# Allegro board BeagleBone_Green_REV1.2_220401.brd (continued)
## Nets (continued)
Pads without a net: J1 2 3 6; NOREF#4 1; NOREF#8 1; NOREF#13 1; NOREF#15 1; NOREF#22 1; NOREF#23 1; NOREF#26 1; NOREF#32 1; NOREF#33 1; NOREF#34 1; NOREF#35 1; NOREF#37 1; NOREF#38 1; NOREF#39 1; P2 6; P5 7; P10 S2; U2 14 15 16 17 35 36 37 38 44; U3 1; U5 F16 M5 M15 P18; U6 1; U9 3 5; U10 5; U12 J1 J9 L1 L9; U13 A1 A2 A7 A8 A9 A10 A11 A12 A13 A14 B1 B7 B8 B9 B10 B11 B12 B13 B14 C1 C3 C5 C7 C8 C9 C10 C11 C12 C13 C14 D1 D2 D3 D4 D12 D13 D14 E1 E2 E3 E5 E8 E9 E10 E12 E13 E14 F1 F2 F3 F10 F12 F13 F14 G1 G2 G3 G10 G12 G13 G14 H1 H2 H3 H5 H12 H13 H14 J1 J2 J3 J12 J13 J14 K1 K2 K3 K6 K7 K10 K12 K13 K14 L1 L2 L3 L12 L13 L14 M1 M2 M3 M7 M8 M9 M10 M11 M12 M13 M14 N1 N3 N6 N7 N8 N9 N10 N11 N12 N13 N14 P1 P2 P7 P8 P9 P10 P11 P12 P13 P14; U16 1

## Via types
v1: diameter 0.457, hole 0.203, TOP to BOTTOM, 899 vias
v2: diameter 0.559, hole 0.305, TOP to BOTTOM, 20 vias

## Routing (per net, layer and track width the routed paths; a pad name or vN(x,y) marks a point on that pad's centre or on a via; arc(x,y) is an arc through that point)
DGND: length 387.2
  TOP w0.076: U13.N2 27.05,44.91 26.85,44.91 26.84,44.91 26.7,44.91 26.69,44.92 26.33,44.92
  TOP w0.178: U13.N5 27.02,43.44 U13.P4
  TOP w0.191: U10.4 v1(14.1,41.41)
  TOP w0.203: U13.C4 32.06,43.43 32,43.43 v1(31.78,43.2) ; U13.H10 29.7,40.56 29.7,40.28 29.84,40.13 29.84,40.11 v1(29.85,40.11) ; v1(31.75,42.01) 31.71,42.05 31.41,42.05 U13.E7 ; U13.P4 25.58,43.66 v1(25.1,44.15) ; v1(28.25,41.66) 28.26,41.66 U13.K8 ; U2.41 v1(23.46,19.62) ; U2.30 24.46,15.04 24.26,15.24 v2(23.88,15.24) ; U13.P6 26.18,42.66 v1(26.04,42.52) ; v1(33.81,42.12) 33.3,42.63 U13.A6 ; v1(25.5,44.7) 26.11,44.7 26.33,44.92 ; U13.G5 30.24,43.16 29.79,43.6 v1(29.79,43.69) 29.5,43.69 29.3,43.48 U13.J5
  TOP w0.254: U5.M7 v1(48.12,30.81) U5.M6 ; v1(46.52,30.01) U5.K9 ; v1(44.92,31.61) U5.M10 ; U5.V18 38.99,36.08 v1(38.99,36.83) ; U12.B9 v1(67.1,30.37) U12.A9 ; v1(61.5,30.37) U12.B3 ; U5.K7 U5.J7 v1(48.12,28.41) ; U12.E2 v1(60.7,27.97) U12.D1 ; U5.J11 v1(44.12,28.41) ; U5.N14 v1(41.72,31.61) U5.M14 ; U5.L13 v1(43.32,30.81) U5.L12 ; v1(66.3,27.97) U12.E8 ; v1(48.12,32.41) U5.N7 ; U5.L10 v1(44.92,30.01) ; v1(44.92,30.01) U5.K10 ; v1(44.92,30.01) U5.K11 ; v1(59.9,30.37) U12.B1 ; v1(46.52,28.41) U5.J9 ; v1(66.3,28.77) U12.D8 ; U5.N10 v1(44.92,32.41) U5.N11 ; U5.H9 v1(46.52,27.61) U5.G8 ; R30.1 v1(51.71,17.75) ; U5.L11 v1(44.12,30.81) U5.M12 ; U5.G11 44.36,27.05 43.88,27.05 U5.G12 v1(43.32,26.81) ; U5.H7 v1(48.12,27.61) ; v1(43.32,27.61) U5.H12 ; U12.G1 59.31,26.96 59.31,27.3 59.69,27.69 60.18,27.69 U12.E1 v1(60.7,27.17) ; U5.H6 v1(48.92,28.41) U5.J6 ; v1(66.3,26.37) U12.G8 ; v1(67.1,19.96) U12.P9 ; U5.J10 v1(44.92,28.41) U5.H10 ; v1(59.9,18.36) U12.T1 ; U12.F9 v1(67.1,26.37) U12.G9 ; U5.M8 v1(46.52,31.61) U5.M9 ; U5.F8 v1(46.52,26.81) U5.G9 ; v1(47.32,28.41) U5.J8 ; v1(66.3,23.96) U12.J8 ; U5.A1 v1(52.52,21.72) ; v1(67.1,18.36) U12.T9 ; v1(59.9,21.56) U12.M1 ; v1(67.1,21.56) U12.M9 ; U5.A18 v1(38.52,22.01) ; v1(52.6,36.58) 52.52,36.49 U5.V1 ; v1(47.32,27.61) U5.H8 ; v1(60.7,23.96) U12.J2 ; v1(59.9,19.96) U12.P1
  TOP w0.381: 37.34,40.01 v1(37.34,39.88) 37.47,39.75 C159.2 38.61,39.75 38.73,39.62 ; 56.52,12.8 56.49,12.83 C96.1 C155.1 55.63,11.68 55.73,11.68 v1(56.01,11.4) ; v1(30.25,9.91) 30.66,9.91 30.88,9.69 U16.3 ; 20.57,41.05 20.95,41.43 R79.2 ; 20.57,41.05 22.58,41.05 v1(23.6,40.03) ; 20.57,41.05 19.02,41.05 18.8,41.27 R78.2 ; R84.2 v1(56.26,45.92) ; v1(20.95,7.24) 20.95,8.26 C1.1 21.59,8.13 v1(21.59,7.24) ; C24.2 44.2,15.06 v1(44.2,14.1) ; v1(22.1,21.34) 21.46,20.7 21.46,20.32 ; S1.3 v1(7.95,50.47) ; R81.2 52.96,42.8 v1(53.09,42.67) ; R118.2 30.53,24.89 v1(30.68,24.74) 31.19,24.74 31.62,24.31 C5.2 ; R118.2 29.97,24.26 ; R118.2 29.46,24.89 ; Y3.4 22.68,26.64 v1(22.28,26.24) 22.28,24.38 22.76,23.9 27,23.9 ; v1(26.99,7.11) 26.99,8.19 C12.1 26.61,8.32 26.29,8 26.29,7.18 v1(26.35,7.11) ; v1(34.29,6.48) C29.2 ; 29.59,19.56 29.46,19.43 27.69,19.43 ; S3.1 v1(7.95,44.37) ; R25.2 36.39,9.08 36.07,8.76 v1(36.07,8.57) ; 27,23.9 27.02,23.92 Y3.2 ; 27,23.9 27.81,23.9 28.19,24.28 v1(28.19,26.24) ; C61.1 v1(75.06,48.39) ; R95.2 75.95,46.23 v1(76.45,45.72) ; 21.97,43.05 R77.2 21.72,44.45 21.34,44.83 21.34,45.34 v1(21.21,45.47) 20.7,45.47 20.59,45.35 Q1.4 ; R80.2 v1(53.98,45.85) ; S2.4 v1(72.14,42.75) ; S2.2 v1(75.69,42.75) ; C18.2 v1(18.29,19.56) ; R93.2 R92.2 72.39,46.35 v1(71.75,45.72) ; Q1.1 19.29,43.63 v1(18.57,44.35) 18.44,44.48 18.08,44.48 17.92,44.64 Q2.4 ; U3.3 v1(40.99,43.43) ; v1(73.79,45.85) 74.17,46.23 R94.2 ; v1(46.35,12.59) R165.2 ; C6.2 v1(44.58,41.71) ; Q2.1 16.62,43.65 16.41,43.87 v1(15.93,43.87) ; S1.1 v1(7.95,51.36) ; S3.3 v1(8.89,39.73) ; C57.1 v1(55.12,48.46)
  TOP w0.508: C24.2 44.3,15.95 D7.1
  TOP w0.889: Y4.2 41.43,42.1 ; Y4.2 40.78,42.66 ; Y4.2 40.78,41.54
  LYR2_GND w0.889: P9.2 20.42,5.18 ; P9.2 18.95,5.18 ; P9.2 20.42,3.71 ; 16.54,7.39 TP8.1 ; TP8.1 18.01,7.39 ; TP8.1 16.54,8.86 ; TP8.1 18.01,8.86 ; P9.44 73.76,5.18 ; P9.44 73.76,3.71 ; P9.44 72.29,3.71 ; P9.44 72.29,5.18 ; 74.83,3.71 P9.46 ; P9.46 76.3,5.18 ; P9.46 74.83,5.18 ; 59.44,11.4 TP1.1 ; TP1.1 60.91,9.93 ; TP1.1 59.44,9.93 ; TP1.1 60.91,11.4 ; 18.72,51.13 P8.1 ; P8.1 18.72,49.2 ; P8.1 20.65,49.2 ; P8.1 20.65,51.13 ; 9.62,8.97 P3.4 ; P3.4 9.62,7.65 ; P3.4 10.95,7.65 ; P3.4 10.95,8.97 ; 73.76,2.64 P9.43 72.29,2.64 ; 16.41,26.13 P5.8 ; P5.8 17.88,24.67 ; P5.8 16.41,24.67 ; P5.8 17.88,26.13 ; 18.95,51.97 P8.2 20.42,51.97 ; 41.58,6.65 J1.1 ; J1.1 43.51,6.65 ; J1.1 41.58,8.59
  LYR2_GND w1.27: P9.45 P9.46 ; P8.2 P8.1 ; P9.43 P9.44 ; P9.1 P9.2
  LYR5_PWR w0.889: 74.83,3.71 P9.46 ; P9.46 76.3,3.71 ; P9.46 74.83,5.18 ; P9.46 76.3,5.18 ; 73.76,2.64 P9.43 72.29,2.64 ; 72.29,3.71 P9.44 ; P9.44 73.76,5.18 ; P9.44 73.76,3.71 ; P9.44 72.29,5.18
  BOTTOM w0.191: C88.2 45.71,23.5 44.92,24.3 v1(44.92,24.41) ; v1(29.21,32.7) 29.21,32.35 29.34,32.23 30.86,32.23 30.99,32.1 R115.2
  BOTTOM w0.203: C100.2 48.81,25.94 49.26,25.5 49.43,25.5 v1(49.72,25.21) ; v1(13.56,6.81) 12.06,8.31 R173.2
  BOTTOM w0.254: 70.74,15.93 R146.1 ; R146.1 70.74,17.6 ; R146.1 69.96,16.76 ; C70.1 42.63,26.12 v1(43.32,26.81) v1(43.32,27.61) ; v1(54.48,10.16) 53.21,10.16 52.83,10.54 52.83,11.43 52.08,12.18 U15.4 50.28,12.18 50.04,11.94 50.04,10.92 50.28,10.68 U15.1 ; C155.1 55.75,11.94 56.01,11.68 v1(56.01,11.4) ; v1(12.83,15.75) 13.22,15.36 U9.4 ; C127.2 v1(25.4,40.64) ; v1(31.75,42.01) 31.14,41.4 C129.2 ; v1(28.25,41.66) 29.01,42.42 C128.2 ; 14.1,17.02 v1(13.21,17.02)
  BOTTOM w0.305: C43.2 47.43,32.41 v1(48.12,32.41) C73.1 ; C46.2 44.63,29.72 v1(44.92,30.01) ; C48.2 47.83,28.7 v1(48.12,28.41) ; C60.1 v1(43.32,27.61) ; C94.2 v1(44.12,30.81) ; C63.2 44.01,26.81 v1(43.32,26.81) ; v1(46.52,30.01) 45.83,30.01 C47.2 ; C66.2 41.72,30.92 v1(41.72,31.61) 41.72,32.3 C41.2 ; v1(44.92,28.41) 45.58,28.41 C49.2 ; v1(48.12,30.81) C97.2 ; C72.1 46.23,26.52 v1(46.52,26.81) ; v1(46.52,31.61) 46.23,31.9 C42.2 ; v1(48.92,28.41) 48.92,29.1 C98.2 ; C99.2 v1(48.12,27.61) ; C50.2 v1(47.32,27.61)
  BOTTOM w0.381: 33.78,20.33 33.78,21.21 C62.1 33.02,21.21 33.02,20.33 ; 33.78,20.33 C64.2 ; 33.78,20.33 33.02,20.33 ; C81.2 47.88,37.54 v1(47.32,38.1) 46.99,37.77 C84.2 ; 33.02,20.33 v1(33.02,20.32) ; C71.1 38.73,37.08 v1(38.99,36.83) ; C115.2 69.49,29.57 v1(69.82,29.24) ; D6.1 v1(10.77,48.18) ; R117.2 R116.2 v1(31.75,27.94) ; R132.1 R130.1 v1(6.22,30.12) R135.2 v1(6.22,28.88) ; C126.1 23.5,40.13 v1(23.6,40.03) ; C137.2 11.77,34.07 11.77,33.91 12.02,33.66 v1(12.06,33.66) ; v2(22.61,13.97) 22.61,13.44 C146.2 ; R83.2 v1(60.71,43.31) ; v1(18.64,48.77) 18.16,48.29 U4.6 ; R90.2 v1(67.77,44.07) R91.2 ; v1(14.27,11.86) 14.27,12.4 14.78,12.9 C2.1 v1(15.34,11.81) ; C107.2 v1(57.15,31.17) ; C59.2 C90.2 C91.2 C89.2 C105.2 C92.2 ; C111.2 v1(57.15,23.16) ; v1(36.83,33.66) 37.15,33.97 R49.1 ; v1(40.64,39.62) 39.75,40.51 38.86,40.51 ; R88.2 R87.2 v1(64.14,43.31) ; v1(16.54,37.41) 16.13,37.82 R10.2 ; v1(36.83,26.81) C54.2 ; C54.2 C44.2 ; C54.2 C79.2 C69.1 ; v1(12.67,43.69) C36.2 13.46,44.2 v1(13.21,44.45) ; v1(30.23,37.08) 29.65,37.66 U1.3 ; v1(49.21,18.41) 50.87,18.41 51.12,18.66 R54.1 ; v1(49.21,18.41) C104.2 C92.2 ; v1(49.21,18.41) R164.2 ; v1(31.78,43.2) 32.39,43.81 C130.2 ; R12.1 v1(3.12,17.4) ; v1(5.84,45.82) 5.83,45.82 5.44,45.43 P4.5 ; P2.20 39.56,18.73 40.53,17.76 40.53,16.27 40.24,15.98 39.5,15.98 39.35,16.13 38.01,16.13 P2.16 v1(36.07,16.19) ; C56.1 45.72,35.53 45.82,35.63 v1(45.82,36.83) 44.45,36.83 43.96,37.32 C106.2 C58.2 ; U4.8 v1(20.7,48.16) ; v1(22.28,26.24) C142.2 ; v1(17.42,37.39) 17.02,37.8 C19.2 ; C109.2 v1(57.15,27.17) ; v1(3.73,16.7) 4.37,16.07 C35.2 ; C30.2 30,10.16 v1(30.25,9.91) ; v1(36.7,35.66) 36.75,35.61 37.21,35.61 37.58,35.24 C86.2 ; C117.2 69.35,25.57 v1(69.88,25.04) ; C143.2 v1(28.19,26.24) ; C92.2 v1(48.26,18.53) ; R82.2 v1(59.18,44.07) ; v1(5.31,6.55) 4.7,6.55 R53.2 ; R99.1 v1(69.85,21.96) ; v1(37.34,39.88) 37.11,39.88 U6.3 ; C38.2 C67.2 v1(33.02,35.56) ; C78.2 35.05,33.91 v1(35.56,33.91) ; v1(36.83,30.81) 36.87,30.77 37.55,30.77 C87.2 C45.2 ; v1(40.99,43.43) 40.69,43.73 C158.2 ; C114.2 v1(69.09,31.75) ; C108.2 v1(57.15,29.57) ; R29.1 49.17,38.86 48.92,38.61 v1(48.92,38.1) C68.1 ; v1(29.46,20.7) 29.46,21.46 29.91,21.91 U7.2 ; C141.2 v1(10.67,30.48) ; C61.1 v1(75.06,48.39) ; v1(5.59,9.78) 5.59,8.96 5.6,8.95 U8.1 ; C119.2 v1(69.85,24.36) ; P2.12 P2.10 36.32,12.38 36.07,12.13 v1(36.07,11.18) 36.13,11.11 P2.8 ; C77.2 33.34,37.08 v1(32.38,37.08) ; C110.2 v1(57.15,25.57) 57.06,25.65 R22.1 ; v1(66.3,23.96) U12.J8 C123.2 ; v1(62.99,21.21) C124.2 R100.2 ; C121.2 v1(69.85,19.16) ; v1(69.93,25.93) 70.1,26.11 C118.1 ; C135.2 27.81,33.66 27.84,33.63 v1(27.99,33.63) ; v1(41.35,38) 41.35,37.81 41.32,37.78 C80.2 ; 70.7,34.56 P10.6 v1(69.22,34.56) ; R144.2 v1(18.73,28.26) ; U4.7 v1(19.43,48.15) ; v1(50.16,38.1) 50.52,37.74 C74.1 ; v1(36.83,24.89) 36.84,24.89 36.96,24.77 C82.2 C83.2 C85.2 ; v1(17.6,49.12) 16.89,48.41 U4.5 ; v1(76.33,26.16) R147.1 v1(75.31,25.15) ; C17.2 C20.2 18.92,37.44 v1(18.87,37.39) 18.87,35.23 19.3,34.8 20.83,34.8 21.46,35.43 21.46,37.85 21.84,38.23 C27.2 24.84,38.28 C23.2 ; v1(31.24,40.13) 31.75,40.64 C145.2 C144.2 ; R86.2 v1(62.87,43.23) ; 25.91,30.48 26.16,30.23 C136.2 ; C75.1 v1(53.09,48.39) ; C113.2 v1(57.15,19.16) ; R85.2 v1(61.98,43.31) ; C154.2 v1(66.17,36.58) ; C140.2 v1(10.67,27.94) ; R145.2 v1(31.75,34.61) ; P2.4 v1(36.07,8.57) ; C112.2 v1(57.15,20.76) ; C152.2 v1(26.04,23.06) ; C138.2 v1(10.67,33.02) ; C139.2 v1(10.67,31.75) ; C120.2 v1(69.85,20.76) ; 65.91,37.97 v1(64.9,37.97) ; C116.2 v1(69.8,28.57) 71.68,28.57 72.19,29.09 P10.9 ; R89.2 v1(66.29,43.33) ; C125.2 v1(32.38,48.26) ; C28.2 v1(57.15,28.41) ; R96.1 v1(69.85,23.16) ; 43.43,14.86 v1(43.43,14.1) v1(44.2,14.1) 44.2,14.86 FB3.2 43.43,14.86
  vias: v1(3.81,32.13) v1(6.2,46.15) v1(6.43,45.72) v1(6.73,46.08) v1(6.99,28.7) v1(8.99,44.22) v1(12.61,19.12) v1(13.11,19.38) v1(15.62,16.26) v1(28.57,2.13) v1(29.97,18.03) v1(29.97,17.4) v1(31.06,2.08) v1(33.02,27.37) v1(33.02,26.54) v1(33.02,24.38) v1(39.98,41.33) v1(52.83,18.41) v1(55.37,16.76) v1(58.72,35.1) v1(60.2,35.05) v1(61.72,9.02) v1(61.85,11.05) v1(61.98,35.05) v1(63.17,15.82) v1(64.01,8.26) v1(65.41,10.67) v1(65.51,15.88) v1(67.64,8.05) v1(69.9,7.52) v1(71.5,6.22) v1(74.55,13.34) v1(74.8,6.22) v1(76.96,37.97) v1(79.63,38.86) v1(81.03,13.72) v1(81.15,22.35) v1(81.15,19.3) v1(81.15,15.49) v1(81.53,32.77) v1(81.79,37.08) v1(81.79,35.43) v1(81.92,26.04) v1(82.35,14.71) v1(83.06,37.21) v1(83.31,35.2) v1(83.29,33.3) v1(83.34,22.15) v1(83.36,25.91) v1(83.57,17.91) v2(3.99,11.71) v2(3.99,10.44) v2(5.26,11.71) v2(5.26,10.44) v2(21.51,13.56) v2(22.61,15.24) v2(24.13,31.11) v2(25.08,32.07) v2(25.08,31.11) v2(25.08,30.16) v2(26.04,31.11) v2(50.93,45.34) v2(51.69,46.23)
GND_EARTH: length 15.3
  BOTTOM w0.762: P4.9 3.16,47.35 3.34,47.53 P4.6 ; P10.S1 82.88,43.71 83.03,43.87
  vias: v1(0.79,33.68) v1(0.79,30.23) v1(0.81,22.07) v1(0.79,14.86) v1(0.81,8.18) v1(0.94,36.45) v1(0.94,18.64) v1(0.86,11.79) v1(0.99,25.68) v1(1.07,4.88) v1(1.24,50.62) v1(1.22,49.3) v1(1.19,45.62) v1(1.42,43.21) v1(1.37,39.34) v1(2.24,51.94) v1(2.24,51.28) v1(2.18,50.57) v1(2.18,49.91) v1(2.24,49.17) v1(2.29,23.19) v1(2.26,3.2) v1(3.35,40.44) v1(3.89,38.63) v1(4.52,39.4) v1(5.24,38.61) v1(5.71,40.39) v1(7.57,2.33) v1(8.31,20.68) v1(9.78,1.17) v1(11.3,2.67) v1(17.04,53.54) v1(17.04,1.07) v1(21.26,0.69) v1(23.65,53.92) v1(26.09,0.66) v1(28.63,53.98) v1(31.34,0.61) v1(33.58,53.95) v1(36.25,0.61) v1(38.71,53.95) v1(41.45,0.64) v1(43.74,53.95) v1(46.33,0.61) v1(48.97,53.92) v1(51.38,0.61) v1(54.13,53.98) v1(56.34,0.56) v1(59.05,53.92) v1(61.49,0.61) v1(64.26,53.92) v1(66.45,0.64) v1(69.29,53.92) v1(71.37,0.61) v1(74.4,53.95) v1(77.27,1.88) v1(77.52,52.58) v1(77.8,49.73) v1(83.34,45.75) v1(83.46,8.84) v1(84,43.92) v1(84.79,11.3) v1(84.94,41.78) v1(84.91,36.91) v1(84.89,32.18) v1(84.99,40.13) v1(85.09,26.7) v1(85.14,25.27) v1(85.12,14.66) v1(85.24,34.87) v1(85.24,29.34) v1(85.17,22.25) v1(85.24,16.54) v1(85.55,31.7) v1(85.5,19.08)
GND_OSC0: length 30.3
  TOP w0.121: 44.52,36.83 U5.V11
  TOP w0.381: v1(44.3,38.66) 44.3,37.69 44.52,37.47 44.52,36.83
  BOTTOM w0.381: 47.84,44.05 Y2.4 49.11,44.05 49.53,43.64 49.53,41.61 48.74,40.82 C25.2 48.11,39.85 R29.2 48.16,39.23 47.71,38.79 47.09,38.79 46.69,38.38 45.09,38.38 44.81,38.66 v1(44.3,38.66) 43.18,39.78 43.18,44.15 43.99,44.96 46.93,44.96 47.84,44.05 ; 47.84,44.05 46.74,42.96 46.55,42.96 45.79,42.2 Y2.2 45.3,42.57 C26.2
GND_OSC1: length 3.3
  TOP w0.254: 50.16,18.36 50.15,18.35 R30.2 C21.1 ; 49.73,22 U5.A5
  TOP w0.381: C22.1 C21.1
GNDA_ADC: length 46.7
  TOP w0.254: v1(47.32,25.21) U5.E8
  TOP w0.305: 46.12,21.97 U5.A9
  TOP w0.381: C32.2 C31.2 C33.2 C93.2 ; C93.2 v1(45.09,16.51) ; C93.2 45.85,17.27 46.48,17.91 46.48,21.59 46.12,21.95 46.12,21.97
  LYR4 w0.381: v1(47.32,25.21) 46.29,25.21 45.85,24.77 45.85,23.24 46.48,22.61 46.48,20.32 45.09,18.92 v1(45.09,16.51) 45.59,16.51 47.83,14.27 47.83,11.1 49.76,9.17 51.23,9.17 51.56,8.84 53.01,8.84 53.95,7.9 53.95,7.39 56.52,4.82 56.52,4.19 57.34,3.37 59.25,3.37 P9.34
  BOTTOM w0.381: FB3.1 44.84,17.14 45.09,16.89 v1(45.09,16.51)
VBUS: length 2.4
  BOTTOM w0.629: 9.42,16.18 P3.1 9.42,14.45
VDD_1V8: length 34.6
  TOP w0.203: 24.27,19.81 23.82,19.36 23.82,18.87 23.86,18.83 U2.40
  TOP w0.254: U5.E9 U5.D10 v1(44.92,25.21) ; v1(40.08,33.99) 40.14,33.99 U5.R16 ; v1(40.12,32.41) U5.N16
  TOP w0.381: 24.27,19.81 25.34,19.81 v1(26.68,18.47) 26.68,18.46 26.68,17.92 v1(26.67,17.91)
  LYR3 w0.381: v1(26.67,17.91) 26.68,17.92 26.68,18.46 v1(26.68,18.47)
  BOTTOM w0.305: v1(40.08,33.99) 39.76,34.31 39.76,34.37 39.32,34.81 39.12,34.81 38.69,35.24 C86.1 ; v1(44.92,25.21) 45.61,24.52 C88.1
  BOTTOM w0.381: 17.4,18.8 18.54,18.8 20.07,20.32 24.51,20.32 25.4,19.43 25.4,18.35 C14.2 ; C14.2 26.04,18.35 26.4,18.35 26.46,18.41 26.63,18.41 26.68,18.46 ; C14.2 25.96,17.79 26.56,17.79 v1(26.67,17.91) 26.68,17.92 26.68,18.46 ; v1(33.02,33.91) 33.53,33.91 C78.1 33.4,33.27 v1(33.02,33.27) 33.02,32.89 33.78,32.13 FB1.1 ; v1(26.68,18.47) 26.68,18.46 ; 45.09,14.15 45.09,14.99 45.34,15.24 FB2.2 46.35,14.44 45.97,14.06 v1(45.88,14.06) 45.1,14.06 v1(45.06,14.1) 45.06,14.12 45.09,14.15
VDD_3V3A: length 114.2
  TOP w0.203: U2.43 22.66,18.81 22.36,19.11 v1(22.36,19.62)
  TOP w0.254: U5.P6 v1(48.92,33.21) ; v1(48.12,33.21) U5.P7 U5.P8 ; U5.P10 v1(44.92,33.21) U5.P11 ; U5.F14 v1(41.72,26.81) U5.G14 ; U5.K14 v1(42.52,30.01) U5.L14 ; U5.E13 v1(43.32,25.21) U5.E12 v1(44.12,25.21) U5.E11 v1(44.92,26.01) U5.E10 ; U5.P5 v1(49.72,33.21) ; U5.N5 v1(49.72,31.61) ; U5.J14 v1(41.72,28.41) U5.H14 ; v1(40.91,34.02) U5.R15 ; v1(40.92,32.41) U5.N15 ; U5.P12 v1(43.32,33.21) ; U5.P13 v1(42.52,33.21)
  TOP w0.381: C61.2 75.06,46.23 v1(75.56,45.72) ; R3.1 R4.1 ; R4.1 v1(26.99,23.11) ; R4.1 C37.1 ; U3.5 39.69,45.76 38.89,44.96 v1(38.89,44.12) ; R1.1 23.62,20.57 v1(24.38,21.34) ; Y4.4 38.93,40.45 38.61,40.77 C159.1 37.57,40.77 v1(37.34,40.53) ; v1(53.09,45.85) R56.1 ; v1(55.12,45.95) C57.2
  LYR3 w0.381: v1(3.17,16.26) 5.46,13.97 10.92,13.97 11.81,14.86 15.29,14.86 16.51,16.08 16.51,17.91 17.02,18.41 21.34,18.41 22.36,19.44 v1(22.36,19.62) ; v1(25.4,40.01) 25.91,39.5 34.39,39.5 35.28,38.61 v1(35.69,38.61)
  BOTTOM w0.305: v1(41.72,28.41) 41.72,27.72 C60.2 41.72,27.5 v1(41.72,26.81) 41.72,26.12 C70.2 ; C72.2 45.43,25.5 v1(44.92,26.01) ; v1(44.92,33.21) 45.61,33.9 C56.2 ; C66.1 42.63,30.12 v1(42.52,30.01) ; C87.1 39.14,30.73 39.81,31.41 39.92,31.41 v1(40.92,32.41)
  BOTTOM w0.381: R52.1 v1(3.17,16.26) ; v1(25.4,40.01) 24.38,40.01 23.75,39.37 22.99,39.37 22.23,40.13 22.23,40.64 21.59,41.27 U4.1 ; C158.1 39.22,44.4 38.94,44.12 v1(38.89,44.12) ; R156.1 C152.1 26.99,21.4 ; C67.1 34.8,36.77 C77.1 ; C67.1 C38.1 ; C67.1 v1(35.56,35.56) ; R63.1 65.02,46.13 v1(64.62,45.72) 64.62,45.85 64.14,46.33 R62.1 ; R59.1 55.78,46.61 v1(55.12,45.95) 54.46,46.61 R55.1 R56.1 v1(53.09,45.85) ; 26.99,21.4 26.99,22.19 27,22.2 27,22.6 26.99,22.61 v1(26.99,23.11) ; 26.99,21.4 27.43,20.95 U7.4 ; v1(30.23,12.32) 29.97,12.06 R14.1 ; R65.1 67.18,46.28 v1(66.75,45.85) 66.29,46.3 R64.1 ; v1(49.72,31.61) 49.83,31.72 C73.2 ; v1(75.56,45.72) 75.95,46.1 R70.1 C61.2 R69.1 R68.1 R67.1 R66.1 v1(68.38,45.8) ; C77.1 35.18,38.23 35.56,38.61 v1(35.69,38.61) ; C77.1 35.5,36.83 v1(36.08,36.83) ; 37.72,37.59 37.72,37.08 v1(37.97,36.83) ; R58.1 60.71,46.25 v1(60.27,45.82) 59.82,46.28 R57.1 ; R60.1 61.98,46.33 v1(62.46,45.85) 62.87,46.25 R61.1 ; v1(22.36,19.62) 22.36,19.31 21.97,18.92 C15.2 ; 37.97,40.51 37.36,40.51 v1(37.34,40.53) ; C59.1 v1(43.5,20.95)
VDD_3V3AUX: length 24.8
  TOP w0.203: 19.3,19.75 19.22,19.67 19.22,17.7 19.49,17.44 U2.1
  TOP w0.381: 19.3,19.75 C18.1 19.3,20.7 18.54,21.46 13.84,21.46 8.38,16 5.94,16 4.51,17.44 D1.2
VDD_3V3B: length 169
  TOP w0.203: U13.N4 U13.P3 v1(25.98,44.16) ; v1(30.35,43.69) 30.6,43.45 30.6,43.36 U13.F5 ; v1(28.14,43.65) 28.14,43.66 U13.M4 ; v1(29.2,40.1) 29.2,40.56 U13.J10 ; v1(28.24,40.83) 28.24,40.96 28.45,41.16 U13.K9 ; U13.E6 31.41,42.55 v1(31.6,42.55) 31.6,42.55 31.71,42.66 U13.C6 ; U13.P5 25.79,43.16 25.74,43.21 v1(25.32,43.21)
  TOP w0.254: v1(28.45,30.87) 28,30.87 U14.12
  TOP w0.381: v1(46.84,45.51) 46.84,45 46.89,44.95 R110.1 ; R119.1 v1(31.75,33.66) ; C29.1 v1(34.29,9.84) 34.86,10.41 36.83,10.41 37.47,11.05 37.47,12.64 37.21,12.89 R23.1 36.83,14.1
  TOP w0.635: v2(74.24,32.38) 74.26,32.4 J5.3 ; J4.3 v2(78.55,17.54)
  LYR3 w0.381: v1(66.17,41.22) v1(66.17,40.34) v1(66.17,39.45) ; v1(34.29,9.84) 39.43,9.84 39.62,9.66 41.05,9.66 41.45,10.06 45.95,10.06 46.66,9.35 55.07,9.35 55.37,9.65 v1(55.37,10.16)
  LYR4 w0.381: v1(55.37,10.16) 55.37,12.06 54.36,13.08 v1(54.36,14.24) ; v1(65.66,48.08) 65.28,47.7 65.28,45.34 64.9,44.96 64.9,42.49 v1(66.17,41.22) ; v1(68.59,37.59) 68.2,37.59 v1(66.17,35.56) v1(66.17,34.42) v1(66.17,33.27)
  LYR4 w0.635: v2(78.55,17.54) 74.32,21.77 74.32,21.84 74.24,21.91 v1(74.24,26.75) v2(74.24,32.38) 74.24,34.47 71.12,37.59 v1(69.27,37.59) v1(68.59,37.59)
  LYR5_PWR w0.889: P9.4 22.96,5.18 ; P9.4 21.49,3.71 ; P9.4 21.49,5.18 ; P9.4 22.96,3.71
  LYR5_PWR w1.27: P9.3 P9.4
  BOTTOM w0.191: R112.2 30.99,31.15 30.86,31.27 28.86,31.27 v1(28.45,30.87)
  BOTTOM w0.203: R11.1 17.95,38.1 18.31,38.46 18.31,38.55 18.88,39.12 C20.1
  BOTTOM w0.254: v1(30.35,43.69) 30.35,43.19 30.48,43.06 C129.1 30.87,42.42 31.01,42.55 v1(31.6,42.55) ; v1(25.32,43.21) 25.4,43.13 C127.1 ; U15.7 55.11,11.18 C155.2 55.13,10.68 U15.8 ; v1(28.24,40.83) 28.57,41.16 28.57,41.16 28.82,41.4 C128.1 29.21,40.76 29.2,40.74 v1(29.2,40.1)
  BOTTOM w0.381: R106.1 44.73,46.1 v1(44.73,46.08) R109.1 ; R111.1 v1(26.67,48.13) ; R163.1 47.94,14.82 48.89,13.88 54,13.88 v1(54.36,14.24) ; R34.1 31.14,37.19 v1(31.24,37.08) ; R152.1 v1(66.17,35.56) ; C135.1 26.16,33.15 v1(28.45,30.87) ; R150.1 v1(66.17,41.22) ; C155.2 v1(55.37,10.16) ; 24.89,36.77 R35.1 24.26,37.34 ; R108.1 25.02,46.12 24.97,46.07 v1(24.97,45.77) ; R155.1 v1(66.17,40.34) ; R157.2 v1(74.24,26.75) ; R177.1 R178.1 72.14,18.96 73.56,17.54 v2(78.55,17.54) ; U6.5 34.43,41.67 34.29,41.53 C144.1 33.19,41.74 33.19,41.91 33.02,42.08 C130.1 32.35,42.8 32.11,42.55 v1(31.6,42.55) ; R101.1 R102.1 49.3,45.87 v1(49.3,45.87) ; R153.1 v1(66.17,34.42) ; R103.1 v1(28.35,45.8) ; R154.1 v1(66.17,33.27) ; P2.5 v1(34.29,9.84) ; R104.1 v1(30.86,45.77) ; U1.5 26.59,39.04 26.49,39.14 C23.1 25.85,39.71 26.04,39.89 v1(26.04,40.13) ; R114.2 R112.2 ; R151.1 v1(66.17,39.45) ; v1(46.84,45.51) 46.84,45.82 46.79,45.87 R105.1 ; C20.1 18.92,39.18 18.16,39.94 U4.3 18.16,41.91 19.05,42.8 C126.2 v1(23.5,43.94) v1(23.5,44.53) ; R107.1 v1(23.34,45.81) ; R119.1 v1(31.75,33.66)
  BOTTOM w0.635: 70.7,36.76 P10.4 69.53,36.76 69.47,36.7
VDD_5V: length 6.5
  TOP w0.203: U2.10 18.92,13.84
  LYR4 w0.889: 24.03,5.18 P9.6 ; P9.6 24.03,3.71 ; P9.6 25.5,3.71
  LYR4 w1.27: P9.5 P9.6
  vias: v1(17.93,13.34) v1(17.93,12.85) v1(17.93,12.37)
VDD_ADC: length 33.1
  TOP w0.254: v1(47.32,24.41) U5.D8
  TOP w0.381: v1(45.85,20.95) 45.84,20.95 45.84,20.09 R27.1 45.09,19.34 C93.1 45.72,18.29 v1(45.85,18.41)
  LYR3 w0.381: v1(47.32,24.41) 46.71,25.02 46.23,25.02 45.85,24.64 v1(45.85,20.95)
  LYR4 w0.381: v1(45.85,18.41) 45.85,17.17 48.39,14.63 48.39,11.3 49.96,9.73 53.09,9.73 54.08,8.74 55.65,8.74 57.15,7.24 57.15,5.08 P9.32
  BOTTOM w0.381: v1(45.85,18.41) 45.85,17.65 46.35,17.14 FB2.1
VDD_CORE: length 46.3
  TOP w0.254: U5.H11 v1(44.12,27.61) ; U5.N8 v1(46.52,32.41) U5.N9 ; v1(46.52,30.81) U5.L9 ; U5.M13 v1(42.52,31.61) ; U5.K8 v1(47.32,30.01) U5.L7 ; v1(47.32,30.81) U5.L8 ; U5.J12 v1(43.32,28.41) ; U5.G6 v1(48.92,26.81) U5.F6 ; v1(48.12,26.81) U5.G7 ; U5.M11 v1(44.92,30.81) ; U5.F7 v1(48.12,26.01) ; U5.G10 v1(44.92,27.61) ; U5.K6 v1(48.92,30.01) U5.L6 ; U5.K12 v1(44.12,30.01) ; U5.N12 v1(43.32,31.61) U5.N13
  LYR4 w0.508: v1(32.13,25.4) v1(32.13,24.77) 32.13,23.57 30.73,22.17 30.73,19.18 31.11,18.8 31.11,14.99 v1(29.21,13.08) v1(28.57,13.08)
  BOTTOM w0.305: v1(48.92,30.01) v1(47.32,30.01) U5.K8 46.92,29.32 C48.1 ; C49.1 45.03,27.5 v1(44.92,27.61) ; v1(44.92,30.81) 45.61,30.81 C47.1 45.83,30.81 v1(46.52,30.81) ; C41.1 42.52,32.3 v1(42.52,31.61) v1(43.32,31.61) ; C43.1 v1(47.32,30.81) ; v1(44.12,27.61) v1(43.32,28.41) 43.61,28.7 C46.1 43.61,29.5 v1(44.12,30.01) ; C42.1 45.83,32.81 46.12,32.81 v1(46.52,32.41) ; C50.1 47.43,26.01 v1(48.12,26.01) v1(48.12,26.81) v1(48.92,26.81) ; v1(40.12,30.81) 39.83,30.81 38.86,29.84 C45.1
  BOTTOM w0.381: C44.1 C54.1 v1(39.32,26.81) ; 28.57,13.78 L3.2 29.21,13.78 v1(29.21,13.08) v1(28.57,13.08) 28.57,13.78
  vias: v1(35.56,27.37) v1(35.56,26.81)
VDD_MPU: length 28.7
  TOP w0.254: U5.J13 v1(42.52,28.41) U5.H13 42.81,27.9 42.81,27.32 U5.G13 v1(42.52,26.81) U5.F13 v1(43.32,26.01) U5.F12 U5.F11 44.59,26.48 45.25,26.48 U5.F10
  TOP w0.635: 26.29,11.3 30.48,11.3 33.15,13.97 33.15,17.71 34.92,19.48 34.92,21.08 35.41,21.56
  BOTTOM w0.305: v1(43.32,26.01) 43.43,25.9 C63.1
  BOTTOM w0.381: C62.2 35.31,21.46 v1(36.08,21.46) v1(36.08,22.1) 35.43,22.1 35.18,21.84 C62.2 ; C62.2 34.8,21.21 C64.1 ; v1(42.52,28.41) 42.63,28.52 C65.1
  vias: v1(26.48,9.91) v1(27.11,9.91)
VDD_MPUON: length 10.6
  TOP w0.121: TP2.1 56.27,15.56 55.57,16.26 54.99,16.26 54.48,16.76 54.48,17.65 53.21,18.92 52.7,18.92 52.32,19.3 52.32,20.07 51.72,20.67 U5.A2
VDD_PHYA: length 7
  TOP w0.254: v1(22.73,27.94) 22.99,27.94 23.33,28.28 U14.1 ; v1(21.27,33.02) 21.27,32.77 21.78,32.26 21.78,32.08 22,31.87 U14.27
  BOTTOM w0.381: R122.2 v1(18.73,31.11) ; R123.2 v1(18.73,32.07) ; R120.2 v1(18.73,29.21) ; R121.2 v1(18.73,30.16) ; R137.2 v1(10.67,29.21)
VDD_PLL: length 12.9
  TOP w0.254: v1(44.12,33.21) U5.R11 v1(44.92,34.01) 45.32,33.62 U5.R10 ; v1(48.12,25.21) U5.E7 ; U5.H15 v1(40.92,27.61)
  LYR3 w0.381: v1(44.92,34.01) v1(44.12,33.21) 43.29,32.38 41.66,32.38 41.23,31.96 41.22,31.96 41.14,31.88 40.11,31.88 39.85,31.62 39.85,31.39 39.51,31.05 39.08,31.05 v1(38.52,31.61)
  BOTTOM w0.305: C94.1 v1(44.12,33.21)
  BOTTOM w0.635: FB1.2 37.92,31.61 v1(38.52,31.61)
VDD_RTC: length 5.4
  TOP w0.254: v1(48.92,24.41) U5.D6
  BOTTOM w0.121: v1(48.92,24.41) 49.32,24.01 49.32,23.54 49.32,22.86 48.75,22.29 48.75,20.66 C104.1
VDDS: length 45.9
  TOP w0.254: v1(46.52,26.01) U5.F9 ; v1(46.52,33.21) U5.P9 ; v1(43.32,30.01) U5.K13 ; U5.E6 v1(48.92,25.21) ; U5.E14 v1(41.72,25.21) ; v1(41.72,33.21) U5.P14 ; U5.N6 v1(48.12,31.61)
  LYR5_PWR w0.305: v1(45.72,29.21) 45.47,29.46 43.87,29.46 v1(43.32,30.01)
  BOTTOM w0.121: 41.32,35.26 41.32,33.61
  BOTTOM w0.254: 41.32,33.61 v1(41.72,33.21)
  BOTTOM w0.305: 41.32,35.26 41.45,35.4 41.45,36.17 C80.1
  BOTTOM w0.381: C80.1 41.64,36.3 41.91,36.58 41.91,37.73 42.13,37.95 44.29,37.95 44.89,37.36 46.04,37.36 46.35,37.05 46.35,36.95 46.35,36.94 46.35,36.65 46.58,36.42 46.58,36.32 ; 39.24,22.73 39.24,21.84 38.88,21.48 37.83,21.48 36.32,22.99 33.02,22.99 32.51,23.5 29.97,23.5 29.58,23.89 21.22,23.89 16.99,19.66 16.66,19.66 16.38,19.38 R9.1 R8.2
VDDS_DDR: length 57.5
  TOP w0.254: U5.G5 v1(49.72,26.81) U5.F5 U5.E5 ; v1(67.1,29.57) U12.C9 ; U5.L5 v1(49.72,30.01) U5.K5 ; v1(59.9,19.16) U12.R1 ; v1(67.1,19.16) U12.R9 ; v1(67.1,20.76) U12.N9 ; U5.J5 v1(49.72,28.41) U5.H5 ; v1(59.9,31.17) U12.A1 ; v1(59.9,29.57) U12.C1 ; v1(59.9,27.17) U12.F1 ; v1(66.3,23.16) U12.K8 ; v1(59.9,20.76) U12.N1 ; v1(67.1,25.57) U12.H9 ; v1(67.1,27.97) U12.E9 ; v1(60.7,30.37) U12.B2 ; v1(61.5,27.97) U12.D2 ; v1(66.3,31.17) U12.A8 ; v1(67.1,28.77) U12.D9 ; v1(65.5,26.37) U12.G7 ; v1(60.7,23.16) U12.K2
  TOP w0.305: v1(60.7,25.57) U12.H2
  TOP w0.381: v1(23.24,7.24) 23.24,8.13 C9.2 22.61,8.26 v1(22.61,7.24) ; C96.2 v1(55.37,15.81)
  BOTTOM w0.305: C97.1 49.72,30.7 v1(49.72,30.01) 49.72,29.32 C98.1 49.72,29.1 v1(49.72,28.41) 49.72,27.72 C99.1 49.72,27.5 v1(49.72,26.81) 49.72,26.12 C100.1
  BOTTOM w0.381: R97.1 v1(64.01,18.36) ; R98.1 64.7,25.57 v1(65.5,26.37) ; v1(52.83,20.32) v1(52.83,19.56) 53.59,19.56 C95.2 53.59,20.32 v1(52.83,20.32) ; v1(52.83,20.32) 52.2,20.32 C101.1 ; v1(67.1,25.57) C117.1 67.97,25.67 67.97,26.52 68.33,26.87 C118.2 67.44,27.05 67.1,27.39 v1(67.1,27.97) ; v1(66.3,23.16) 67.5,24.36 C119.1 ; v1(67.1,20.76) C120.1 ; C122.2 v1(66.04,16.83) ; C102.1 C103.1 55.24,15.68 v1(55.37,15.81) ; v1(66.3,31.17) C114.1 C115.1 v1(67.1,29.57) ; C111.1 59.49,22.61 60.14,22.61 v1(60.7,23.16) ; C110.1 59.15,25.57 59.68,26.09 60.12,26.09 60.13,26.09 60.18,26.09 v1(60.7,25.57) ; C116.1 67.29,28.57 v1(67.1,28.77) ; v1(67.1,19.16) C121.1 ; C113.1 v1(59.9,19.16) ; C107.1 v1(59.9,31.17) ; v1(59.9,29.57) C108.1 ; C109.1 v1(59.9,27.17) ; v1(59.9,20.76) C112.1
  BOTTOM w0.406: R6.2 v1(18.8,7.16)
  vias: v1(19.86,7.09) v1(49.91,5.97) v1(50.55,5.97) v1(53.72,5.97) v1(54.36,5.97) v1(57.91,5.97) v1(58.67,5.97) v1(59.44,5.97)
AIN0: length 38.3
  TOP w0.121: U5.B6 48.12,22.81 48.12,22.16 48.51,21.77 48.51,20.45 47.86,19.79 47.86,10.05 48.26,9.65 59.18,9.65 62.61,6.22 65.41,6.22 66.67,4.95 66.67,3.17 P9.39
AIN1: length 32
  TOP w0.121: v1(48.12,23.61) U5.C7
  LYR4 w0.133: P9.40 66.29,6.1 62.2,6.1 57.53,10.77 57.53,16.38 54.76,19.15 52.6,19.15 51.18,20.57 50.42,20.57 48.51,22.48 48.51,23.22 v1(48.12,23.61)
AIN2: length 36.8
  TOP w0.121: P9.37 64.26,3.05 64.26,5.08 63.63,5.71 62.1,5.71 58.67,9.14 47.75,9.14 47.36,9.53 47.36,20.06 48.01,20.7 48.01,21.51 47.32,22.2 47.32,22.81 U5.B7
AIN3: length 33.1
  TOP w0.121: U5.A7 47.72,22.18 48.27,21.63 48.27,20.58 47.61,19.93 47.61,9.79 48.01,9.4 58.93,9.4 62.36,5.97 63.88,5.97 P9.38
AIN4: length 31.1
  TOP w0.121: U5.C8 v1(47.32,23.61)
  LYR4 w0.133: v1(47.32,23.61) 48.13,22.8 48.13,21.34 49.28,20.19 51.16,20.19 52.53,18.82 53.19,18.82 53.34,18.67 54.8,18.67 57.15,16.32 57.15,10.46 61.59,6.02 61.59,3.17 P9.33
AIN5: length 32.4
  TOP w0.121: U5.B8 46.52,22.81 46.52,22.19 46.86,21.84 46.86,9.02 47.24,8.64 58.24,8.64 62.43,4.45 P9.36
AIN6: length 35.8
  TOP w0.121: P9.35 63.88,2.92 63.88,4.95 63.37,5.46 61.85,5.46 58.42,8.89 47.5,8.89 47.12,9.27 47.12,20.19 47.75,20.83 47.75,21.34 46.92,22.17 U5.A8
AIN7: length 10.4
  TOP w0.121: U5.C9 v1(46.52,23.61)
  LYR4 w0.133: v1(48.26,17.97) 48.23,18 48.17,18 47.75,18.41 47.75,22.38 v1(46.52,23.61)
  BOTTOM w0.121: v1(48.26,17.97) 48.26,17.91 47.94,17.59 R163.2 48.39,16.7 48.58,16.51 48.58,15.88 48.77,15.68 R164.1
AM3_MMC1_DAT0: length 13.1
  TOP w0.121: U5.U7 48.12,35.61 48.12,36.44 48.26,36.58 48.26,38.75 48.83,39.32 48.83,44.91 v1(49.23,45.31)
  BOTTOM w0.121: R37.1 51.03,46.45 49.89,45.31 v1(49.23,45.31)
AM3_MMC1_DAT1: length 11
  TOP w0.121: U5.V7 47.72,36.42 48.01,36.7 48.01,38.85 48.58,39.42 48.58,45.58 v1(48.4,45.76)
  BOTTOM w0.121: v1(48.4,45.76) 48.46,45.82 R38.1
AM3_MMC1_DAT2: length 28.8
  TOP w0.121: v1(47.32,34.01) U5.R8
  LYR3 w0.121: v1(47.32,34.01) 46.92,34.41 46.92,35.05
  LYR3 w0.133: 46.92,35.05 46.92,35.12 46.23,35.81 46.23,40.97 40.89,46.3 35.64,46.3 v1(35.18,45.85)
  BOTTOM w0.121: R39.1 29.18,45.64 29.72,45.11 34.44,45.11 v1(35.18,45.85)
AM3_MMC1_DAT3: length 29.1
  TOP w0.121: v1(47.32,34.81) U5.T8
  LYR3 w0.133: v1(47.32,34.81) 47.32,35.23 46.49,36.06 46.49,41.04 46.46,41.07 46.46,41.07 40.99,46.54 40.99,46.54 40.89,46.63 35.53,46.63 v1(34.42,47.75)
  BOTTOM w0.121: v1(34.42,47.75) 33.84,47.75 33.59,47.5 33.59,45.91 33.05,45.36 30.53,45.36 30.02,45.87 R40.1
AM3_MMC1_DAT4: length 12.2
  TOP w0.121: U5.U8 47.32,35.61 47.32,36.4 47.75,36.83 47.75,38.94 48.33,39.52 48.33,45.16 v1(47.62,45.86)
  BOTTOM w0.121: v1(47.62,45.86) R41.1
AM3_MMC1_DAT5: length 17.8
  TOP w0.121: U5.V8 46.92,38.46 47.34,38.88 47.34,39.05 47.09,39.3 47.09,39.47 47.26,39.64 47.43,39.64 47.68,39.39 47.85,39.39 48.08,39.62 48.08,40.18 47.96,40.3 47.43,40.3 47.31,40.42 47.31,40.66 47.43,40.79 47.96,40.79 48.08,40.91 48.08,41.15 47.96,41.27 47.43,41.27 47.31,41.39 47.31,41.63 47.43,41.75 47.96,41.75 48.08,41.87 48.08,42.09 47.96,42.21 47.62,42.21 47.5,42.33 47.5,42.58 47.62,42.7 47.96,42.7 48.08,42.82 48.08,43.06 47.96,43.18 47.62,43.18 47.5,43.3 47.5,43.54 47.62,43.66 47.96,43.66 48.08,43.78 48.08,44.83 46.98,45.94 46.55,45.94 v1(46.28,45.67)
  BOTTOM w0.121: R42.1 45.95,45.97 46.25,45.67 v1(46.28,45.67)
AM3_MMC1_DAT6: length 33.1
  TOP w0.121: v1(46.52,34.01) U5.R9
  LYR3 w0.133: v1(34.37,46.99) 34.37,46.61 34.12,46.36 34.12,45.61 34.9,44.83 36.04,44.83 38.1,42.77 41.63,42.77 43.64,40.76 43.64,36.94 43.64,36.94 43.64,36.89 v1(46.52,34.01)
  LYR4 w0.133: v1(34.37,46.99) 34.09,47.26 25.63,47.26 v1(24.18,45.81)
  BOTTOM w0.121: R43.1 v1(24.18,45.81)
AM3_MMC1_DAT7: length 29.8
  TOP w0.121: v1(46.52,34.81) U5.T9
  LYR3 w0.133: v1(46.52,34.81) 43.87,37.46 43.87,40.86 41.73,43 38.2,43 36.12,45.09 35.31,45.09 v1(34.54,45.85)
  LYR4 w0.133: v1(34.54,45.85) 33.39,47 26.8,47 v1(25.6,45.8)
  BOTTOM w0.121: R44.1 25.83,46.02 v1(25.6,45.8)
B_UART0_RX: length 13.6
  TOP w0.121: R165.1 46.35,7.24 47.12,6.48 49.02,6.48 J1.4
  BOTTOM w0.121: J1.4 52.2,9.65 52.2,10.92 51.94,11.18 U15.2
B_UART0_TX: length 5.2
  BOTTOM w0.121: J1.5 52.7,8.64 52.45,8.89 52.45,11.18 51.95,11.68 U15.3
CAP_VBB_MPU: length 4.2
  TOP w0.121: U5.C10 44.93,23.62 v1(44.92,23.61)
  BOTTOM w0.121: v1(44.92,23.61) 44.92,22.9 45.4,22.42 C91.1
CAP_VDD_SRAM_CORE: length 5.2
  TOP w0.121: U5.D9 v1(46.52,24.41)
  BOTTOM w0.121: v1(46.52,24.41) 46.92,24.01 46.92,23.04 46.35,22.48 C89.1
CAP_VDD_SRAM_MPU: length 5
  TOP w0.121: v1(44.12,24.41) U5.D11
  BOTTOM w0.121: C90.1 44.52,20.26 44.52,24.01 v1(44.12,24.41)
CLKOUT2: length 55.3
  BOTTOM w0.121: P9.41 71.63,3.05 71.63,4.83 69.98,6.48 67.67,6.48 60.71,13.44 43.1,13.44 41.59,14.95 41.59,17.59 42.55,18.54 R20.1 R19.2 41.08,19.68 41.08,20.64 40.89,20.83 40.13,20.83 39.9,20.59 36.28,20.59 35.67,19.98 35.67,17.8 36,17.46 P2.18
CLKOUT_SRC: length 5.1
  TOP w0.121: U5.D14 v1(41.72,24.41)
  BOTTOM w0.121: R19.1 41.59,22.99 41.32,23.26 41.32,24.01 v1(41.72,24.41)
CRS: length 2.7
  TOP w0.121: R139.2 29.51,32.24 28.92,32.24 28.55,31.87 U14.14
DDR_A0: length 23.9
  TOP w0.121: U5.F3 v1(51.32,26.01) ; v1(61.5,20.76) U12.N3
  LYR3 w0.133: v1(53.85,23.11) 53.34,23.11 53.21,22.99 53.21,21.21 54.86,19.56 54.86,19.3 57.02,17.14 61.59,17.14 62.36,17.91 62.36,20.7 61.98,21.08 61.82,21.08 v1(61.5,20.76)
  BOTTOM w0.121: v1(53.85,23.11) 52.58,24.38 52.58,26.16 52.32,26.42 51.73,26.42 v1(51.32,26.01)
DDR_A1: length 24.1
  TOP w0.121: U5.H1 54.54,28.01 56.58,25.97 57.72,25.97 58.93,24.77 v1(58.93,23.88) ; v1(65.5,19.96) U12.P7
  LYR3 w0.121: 60.2,23.87 60.5,23.57 61.67,23.57
  LYR3 w0.133: v1(58.93,23.88) 58.93,23.87 60.2,23.87 ; 61.67,23.57 61.78,23.57 62.23,23.11 62.61,23.11 63.88,21.84 63.88,20.83 63.5,20.45 63.5,18.9 63.63,18.77 64.39,18.77 64.52,18.9 64.52,19.05 64.39,19.18 64.01,19.18 63.88,19.3 63.88,20.19 64.01,20.32 64.14,20.32 64.26,20.19 64.26,19.68 64.39,19.56 64.64,19.56 64.77,19.68 64.77,20.19 64.9,20.32 65.14,20.32 v1(65.5,19.96)
DDR_A2: length 23.9
  TOP w0.121: U5.E4 v1(50.52,25.21) ; v1(61.5,19.96) U12.P3
  LYR3 w0.121: v1(61.5,19.96) 61.1,20.36 61.1,22.09
  LYR3 w0.133: 61.1,22.09 60.83,22.35 59.44,22.35 59.05,21.97 56.77,21.97 56.64,22.1 56.64,23.5 56.77,23.62 57.4,23.62 57.51,23.72 57.51,24.16 57.4,24.26 56.77,24.26 56.64,24.38 56.64,25.4 54.72,27.32 54.5,27.32 54.26,27.08 54.26,26.9 55.12,26.04 55.12,25.15 54.36,24.38 51.12,24.38 50.52,24.98 v1(50.52,25.21)
DDR_A3: length 24
  TOP w0.121: v1(51.32,23.61) U5.C3 ; v1(60.7,20.76) U12.N2
  LYR3 w0.121: 59.61,21.16 60.3,21.16 v1(60.7,20.76)
  LYR3 w0.133: 59.61,21.16 59.56,21.21 56.01,21.21 55.88,21.34 55.88,24.43 55.8,24.51 55.58,24.51 55.5,24.43 55.5,22.2 55.42,22.12 55.07,22.12 54.99,22.05 54.99,21.67 54.91,21.59 54.69,21.59 54.61,21.67 54.61,22.05 54.53,22.12 54.37,22.12 54.29,22.2 54.29,22.4 54.37,22.48 55.04,22.48 55.12,22.56 55.12,22.78 55.04,22.86 54.37,22.86 54.29,22.94 54.29,23.16 54.37,23.24 55.04,23.24 55.12,23.32 55.12,23.53 55.04,23.61 52.96,23.61 52.83,23.48 52.83,22.35 52.7,22.23 52.45,22.23 52.32,22.35 52.32,23.48 52.2,23.61 v1(51.32,23.61)
DDR_A4: length 23.9
  TOP w0.121: v1(56.13,16.26) 56.52,16.64 56.52,17.02 53.72,19.81 53.72,20.57 52.96,21.34 52.96,22.53 52.68,22.81 52.36,22.81 52.12,23.05 52.12,23.61 U5.C2 ; v1(66.3,19.96) U12.P8
  LYR3 w0.121: 65.28,19.56 65.9,19.56 v1(66.3,19.96)
  LYR3 w0.133: v1(56.13,16.26) 56.39,16 62.36,16 63.12,16.76 64.77,16.76 65.02,17.02 65.02,19.3 65.28,19.56
DDR_A5: length 23.9
  TOP w0.121: v1(60.7,19.96) U12.P2 ; U5.B1 52.74,23.21 53.34,22.61 53.34,22.23 53.47,22.1 v1(53.85,22.1)
  LYR3 w0.121: 61.09,18.16 61.1,18.17 61.1,19.56 v1(60.7,19.96)
  LYR3 w0.133: 61.09,18.16 60.83,17.91 59.44,17.91 59.31,18.03 59.31,20.7 59.18,20.83 57.78,20.83 57.66,20.7 57.66,18.41 57.53,18.29 56.9,18.29 56.64,18.54 56.64,20.7 56.52,20.83 56.26,20.83 56.13,20.7 56.13,19.68 56.01,19.56 55.75,19.56 55.63,19.68 55.63,21.64 55.55,21.72 55.32,21.72 55.24,21.64 55.24,21.03 55.17,20.95 54.54,20.95 54.29,21.2 54.29,21.65 v1(53.85,22.1)
DDR_A6: length 24.1
  TOP w0.121: v1(66.3,19.16) U12.R8 ; v1(49.72,24.41) U5.D5
  BOTTOM w0.121: v1(66.3,19.16) 65.9,18.76 65.9,18.15 64.52,16.76 57.28,16.76 55.37,18.67 55.37,21.21 53.98,22.61 53.59,22.61 51.39,24.81 50.12,24.81 v1(49.72,24.41)
DDR_A7: length 24.1
  TOP w0.121: v1(57.15,19.91) 57.63,19.43 58.17,19.43 58.29,19.3 58.29,18.03 58.17,17.91 57.4,17.91 55.63,19.68 55.63,23.88 54.36,25.15 54.36,25.78 54.13,26.01 52.12,26.01 U5.E2 ; v1(60.7,19.16) U12.R2
  BOTTOM w0.121: v1(60.7,19.16) U12.R2 62.23,19.56 62.36,19.69 62.36,20.24 62.23,20.36 59.61,20.36 59.16,19.91 v1(57.15,19.91)
DDR_A8: length 23.9
  TOP w0.121: v1(66.3,18.36) U12.T8 ; v1(50.52,24.41) U5.D4
  BOTTOM w0.121: v1(66.3,18.36) 66.3,18.04 64.64,16.38 57.15,16.38 54.99,18.54 54.99,20.68 54.61,21.06 52.19,21.06 51.94,21.31 51.94,23.75 51.28,24.41 v1(50.52,24.41)
DDR_A9: length 24
  TOP w0.121: U5.C1 53.09,23.44 53.09,23.31 53.79,22.61 54.1,22.61 54.25,22.46 54.25,20.95 54.13,20.83 53.97,20.83 53.85,20.95 v1(53.85,21.46) ; v1(61.5,19.16) U12.R3
  LYR3 w0.133: v1(61.5,19.16) 61.5,19.43 61.63,19.56 61.85,19.56 61.98,19.43 61.98,18.03 61.47,17.53 58.93,17.53 58.8,17.65 58.8,20.32 58.67,20.45 58.29,20.45 58.17,20.32 58.17,17.65 58.04,17.53 57.15,17.53 55.24,19.43 55.24,20.32 54.99,20.57 54.36,20.57 53.85,21.08 v1(53.85,21.46)
DDR_A10: length 24
  TOP w0.121: v1(65.5,22.36) U12.L7 ; U5.F4 v1(50.52,26.01)
  LYR3 w0.121: 51.68,26.41 50.92,26.41 v1(50.52,26.01)
  LYR3 w0.133: v1(65.5,22.36) 65.79,22.65 65.79,22.86 65.66,22.99 64.77,22.99 64.64,23.11 64.64,23.37 64.77,23.5 65.66,23.5 65.79,23.62 65.79,23.88 65.66,24 64.39,24 62.36,26.04 59.31,26.04 57.72,27.62 56.83,27.62 55.75,28.71 52.58,28.71 52.2,28.32 52.2,26.92 51.68,26.41
DDR_A11: length 23.9
  TOP w0.121: U5.F2 52.12,26.81 v1(53.85,26.81) ; v1(65.5,19.16) U12.R7
  BOTTOM w0.121: v1(65.5,19.16) 65.02,19.16 64.77,18.91 64.77,18.16 64.14,17.53 57.53,17.53 56.13,18.92 56.13,23.24 55.88,23.5 54.61,23.5 53.34,24.77 53.34,26.3 v1(53.85,26.81)
DDR_A12: length 24.1
  TOP w0.121: v1(65.5,20.76) U12.N7 ; v1(51.32,25.21) U5.E3
  LYR3 w0.133: v1(65.5,20.76) 63.88,22.38 63.88,23.37 62.23,25.02 61.47,25.02 61.22,24.77 59.56,24.77 57.91,26.42 56.64,26.42 55.12,27.94 53.21,27.94 52.96,27.69 52.96,26.29 53.21,26.04 54.1,26.04 54.36,25.78 54.36,25.4 54.1,25.15 51.38,25.15 v1(51.32,25.21)
DDR_A13: length 24
  TOP w0.121: v1(61.5,18.36) U12.T3 ; U5.H3 v1(51.32,27.61)
  BOTTOM w0.121: v1(61.5,18.36) 63.37,18.36 63.5,18.24 63.5,18.03 63.37,17.91 57.66,17.91 56.52,19.05 56.52,23.62 56.26,23.88 54.74,23.88 54.36,24.26 54.36,27.18 53.92,27.61 v1(51.32,27.61)
DDR_A14: length 24
  TOP w0.121: v1(50.52,27.61) U5.H4 ; v1(65.5,18.36) U12.T7
  BOTTOM w0.121: v1(65.5,18.36) 64.28,17.14 57.4,17.14 55.75,18.8 55.75,21.84 52.96,24.64 52.96,26.8 52.55,27.21 50.9,27.21 50.52,27.58 v1(50.52,27.61)
DDR_A15: length 24
  TOP w0.121: U12.M7 64.52,21.38 64.52,18.11 63.07,16.66 57.35,16.66 54.61,19.41 54.61,23.37 53.57,24.41 51.32,24.41 U5.D3
DDR_BA0: length 24.1
  TOP w0.121: U5.C4 v1(50.52,23.61) ; v1(60.7,21.56) U12.M2
  LYR3 w0.121: 50.92,23.74 50.92,22.48 ; 50.12,22.48 50.12,23.48 50.25,23.61 v1(50.52,23.61)
  LYR3 w0.133: 50.92,23.74 50.92,23.89 51.05,24.02 54.5,24.02 55.5,25.02 55.5,25.65 55.6,25.75 55.78,25.75 56.26,25.27 56.26,21.97 56.64,21.59 59.18,21.59 59.56,21.97 60.57,21.97 60.7,21.84 v1(60.7,21.56) ; 50.12,22.48 50.12,21.46 50.25,21.34 50.42,21.34 50.55,21.46 50.55,21.84 50.67,21.97 50.93,21.97 51.05,21.84 51.05,21.46 51.18,21.34 51.44,21.34 51.56,21.46 51.56,22.23 51.44,22.35 51.05,22.35 50.92,22.48
DDR_BA1: length 24.1
  TOP w0.121: v1(66.3,20.76) U12.N8 ; U5.E1 v1(53.85,25.61)
  LYR3 w0.133: v1(53.85,25.61) 52.62,25.61 52.32,25.91 52.32,26.29 52.58,26.54 52.58,28.07 52.83,28.32 55.37,28.32 56.93,26.76 58.08,26.76 59.69,25.15 61.09,25.15 61.21,25.27 61.21,25.53 61.34,25.65 62.1,25.65 64.23,23.52 64.23,22.63 65.05,21.82 65.66,21.82 65.82,21.65 65.82,21.24 v1(66.3,20.76)
DDR_BA2: length 24.1
  TOP w0.121: v1(51.32,22.81) U5.B3 ; v1(61.5,21.56) U12.M3
  LYR3 w0.133: v1(51.32,22.81) 51.63,23.11 51.82,23.11 51.94,22.99 51.94,20.83 52.07,20.7 52.26,20.7 52.39,20.83 52.39,21.08 52.51,21.21 52.7,21.21 54.48,19.43 54.48,19.18 56.9,16.76 61.98,16.76 62.74,17.53 62.74,20.83 62.48,21.08 62.48,21.34 62.74,21.59 62.74,21.97 62.48,22.23 62.23,22.23 62.1,22.1 62.1,21.69 61.98,21.56 v1(61.5,21.56)
DDR_CASN: length 24
  TOP w0.121: v1(61.5,23.16) U12.K3 ; v1(57.15,22.48) 57.15,21.72 57.28,21.59 58.17,21.59 58.29,21.46 58.29,20.95 58.17,20.83 58.04,20.83 57.91,20.7 57.91,20.45 58.04,20.32 58.17,20.32 58.29,20.19 58.29,19.94 58.17,19.81 57.68,19.81 57.55,19.94 57.55,21.21 57.42,21.34 56.77,21.34 56.64,21.21 56.64,19.81 56.52,19.68 56.13,19.68 56.01,19.81 56.01,24.64 55.88,24.77 55.37,24.77 54.74,25.4 54.74,26.16 54.48,26.41 U5.F1
  LYR3 w0.133: v1(57.15,22.48) 59.05,22.48 59.31,22.73 61.07,22.73 v1(61.5,23.16)
DDR_CKE: length 25.1
  TOP w0.121: U5.G3 v1(51.32,26.81) ; v1(67.1,23.16) U12.K9
  LYR3 w0.133: v1(67.1,23.16) 67.31,23.37 67.31,24.26 67.18,24.38 64.64,24.38 62.61,26.42 59.44,26.42 57.91,27.94 57.02,27.94 55.88,29.08 53.21,29.08 52.83,29.46 51.18,29.46 51.05,29.34 51.05,29.08 51.18,28.96 51.69,28.96 51.82,28.83 51.82,27.3 v1(51.32,26.81)
  BOTTOM w0.121: R96.2 v1(67.1,23.16)
DDR_CLK: length 24
  TOP w0.095: U5.D2 51.98,24.81 52.36,25.2 53.8,25.2 55.27,23.72 55.27,19.67 57.42,17.53 61.58,17.53 63.75,19.7 63.75,23.22 64.74,24.2 64.94,24.2 U12.J7
DDR_CLKN: length 24
  TOP w0.095: U12.K7 65.37,23.56 65.48,23.67 65.48,23.82 65.37,23.92 64.85,23.92 64.03,23.1 64.03,19.58 61.7,17.25 57.3,17.25 54.99,19.56 54.99,23.61 53.68,24.92 52.63,24.92 U5.D1
DDR_CSN: length 23.9
  TOP w0.121: U5.H2 52.12,28.41 54.65,28.41 56.71,26.35 57.85,26.35 59.44,24.77 59.44,23.44 59.36,23.37 58.88,23.37 58.8,23.29 58.8,22.09 59.05,21.84 59.05,18.41 59.18,18.29 59.31,18.29 59.44,18.41 59.44,21.97 59.18,22.23 59.18,22.78 59.26,22.86 59.49,22.86 59.56,22.78 59.56,22.44 59.64,22.36 60.7,22.36 U12.L2
DDR_D0: length 23.3
  TOP w0.121: v1(51.32,31.61) U5.M3 ; v1(62.3,27.97) U12.E3
  LYR3 w0.133: v1(62.3,27.97) 62.3,29.72 62.43,29.84 62.87,29.84 62.99,29.72 62.99,27.43 63.12,27.3 63.63,27.3 63.75,27.43 63.75,29.59 60.45,32.89 52.96,32.89 51.68,31.61 v1(51.32,31.61)
DDR_D1: length 23.3
  TOP w0.121: v1(50.52,31.61) U5.M4 ; v1(65.5,27.17) U12.F7
  LYR3 w0.121: 52.78,30.41 51.16,30.41 50.92,30.64 50.92,31.21 v1(50.52,31.61) ; v1(65.5,27.17) 65.9,26.77 66.47,26.77 66.7,26.53 66.7,25.74 66.7,25.39 66.47,25.16
  LYR3 w0.133: 66.47,25.16 66.08,24.77 64.89,24.77 62.9,26.76 59.6,26.76 57.4,28.96 56.77,28.96 56.26,29.46 53.72,29.46 52.78,30.41
DDR_D2: length 23.3
  TOP w0.121: U12.F2 61.5,27.17 61.98,27.17 61.98,27.17 62.47,27.17 62.73,27.43 62.73,30.61 61.21,32.13 61.21,33.15 61.09,33.27 54.86,33.27 54.74,33.15 54.74,32.89 54.86,32.77 57.02,32.77 57.15,32.64 57.15,31.75 57.02,31.62 55.88,31.62 55.49,32.01 U5.N1
DDR_D3: length 23.3
  TOP w0.121: v1(66.3,27.17) U12.F8 ; U5.N2 52.12,32.41 55.86,32.41 v1(56.13,32.13)
  BOTTOM w0.121: v1(56.13,32.13) 60.83,32.13 62.36,30.61 62.36,29.08 63.18,28.26 63.18,27.69 63.31,27.56 63.5,27.56 63.63,27.69 63.63,28.57 63.75,28.7 64.01,28.7 64.14,28.57 64.14,27.69 64.26,27.56 64.52,27.56 64.64,27.69 64.64,28.57 64.77,28.7 65.58,28.7 65.91,28.37 66.5,28.37 66.7,28.17 66.7,27.57 v1(66.3,27.17)
DDR_D4: length 23.3
  TOP w0.121: U12.H3 63.52,25.17 64.26,25.91 64.26,31.75 63.37,32.64 v1(62.36,32.64) ; U5.N3 v1(51.32,32.41)
  LYR3 w0.133: v1(62.36,32.64) 61.34,33.66 52.58,33.66 51.33,32.41 v1(51.32,32.41)
DDR_D5: length 23.3
  TOP w0.121: v1(66.3,25.57) U12.H8 ; U5.N4 v1(50.52,32.41)
  LYR3 w0.121: v1(50.52,32.41) 50.92,32.01 51.57,32.01
  LYR3 w0.133: 51.57,32.01 52.83,33.27 60.71,33.27 64.26,29.72 64.26,26.04 65.15,25.15 65.88,25.15 v1(66.3,25.57)
DDR_D6: length 23.3
  TOP w0.121: U5.P3 v1(51.32,33.21) ; v1(62.99,32.13) 63.88,31.24 63.88,26.04 63.41,25.56 61.5,25.56 U12.G2
  LYR3 w0.133: v1(51.32,33.21) 51.63,33.21 52.45,34.04 61.59,34.04 62.99,32.64 v1(62.99,32.13)
DDR_D7: length 23.3
  TOP w0.121: v1(65.5,25.57) U12.H7 ; U5.P4 v1(50.52,33.21)
  LYR3 w0.121: v1(50.52,33.21) 50.92,33.61 51.62,33.61
  LYR3 w0.133: v1(65.5,25.57) 64.77,26.3 64.77,31.5 61.87,34.39 52.4,34.39 51.62,33.61
DDR_D8: length 20.3
  TOP w0.121: U5.J1 54.76,28.81 56.83,26.73 58.86,26.73 59.37,26.23 59.37,25.34 59.94,24.77 62.23,24.77 62.36,24.64 62.36,23.24 62.48,23.11 62.99,23.11 64.64,24.77 64.64,27.91 U12.D7
DDR_D9: length 20.3
  TOP w0.121: v1(61.5,29.57) U12.C3 ; v1(56.13,29.97) 55.77,29.61 U5.K1
  LYR3 w0.133: v1(61.5,29.57) 61.5,28.83 61.37,28.7 59.31,28.7 59.18,28.83 59.18,32 59.05,32.13 58.55,32.13 58.42,32 58.42,29.84 58.29,29.72 57.78,29.72 57.66,29.84 57.66,32 57.53,32.13 56.77,32.13 56.64,32 56.64,30.1 56.52,29.97 v1(56.13,29.97)
DDR_D10: length 20.3
  TOP w0.121: v1(66.3,29.57) U12.C8 ; U5.K2 52.12,30.01 v1(53.85,30.01)
  BOTTOM w0.121: v1(53.85,30.01) 54.32,30.01 54.48,29.84 55.12,29.84 55.24,29.97 55.24,32.13 55.75,32.64 60.83,32.64 62.74,30.73 62.74,29.34 62.99,29.08 65.82,29.08 v1(66.3,29.57)
DDR_D11: length 20.1
  TOP w0.121: v1(51.32,30.01) U5.K3 ; v1(60.7,29.57) U12.C2
  BOTTOM w0.121: v1(51.32,30.01) 51.1,29.79 51.1,29.58 51.22,29.46 52.83,29.46 52.96,29.59 52.96,30.23 53.06,30.33 53.3,30.33 53.42,30.21 53.42,29.64 53.59,29.46 55.24,29.46 55.75,28.96 57.44,28.96 57.56,28.84 57.56,28.02 57.81,27.76 60.07,27.76 60.24,27.93 60.24,28.33 60.12,28.45 58.17,28.45 58.04,28.57 58.04,28.83 58.17,28.96 60.88,28.96 61,29.08 61,29.27 v1(60.7,29.57)
DDR_D12: length 20.2
  TOP w0.121: U5.K4 v1(50.52,30.01) ; v1(65.5,31.17) U12.A7
  BOTTOM w0.121: v1(65.5,31.17) 65.5,31.53 63.31,33.72 54.55,33.72 52.58,31.75 52.58,30.16 52.45,30.04 52.2,30.04 52.07,30.16 52.07,30.28 51.94,30.41 50.92,30.41 v1(50.52,30.01)
DDR_D13: length 20.2
  TOP w0.121: v1(60.7,31.17) U12.A2 ; v1(51.32,30.81) U5.L3
  LYR3 w0.133: v1(60.7,31.17) 60.71,31.17 60.71,32 60.17,32.54 53.21,32.54 53.09,32.41 53.09,32 53.21,31.88 55.5,31.88 55.63,31.75 55.63,30.1 55.5,29.97 54.48,29.97 54.36,30.1 54.36,31.11 54.23,31.24 52.07,31.24 51.64,30.81 v1(51.32,30.81)
DDR_D14: length 20.3
  TOP w0.121: v1(66.3,30.37) U12.B8 ; U5.L4 v1(50.52,30.81)
  BOTTOM w0.121: v1(66.3,30.37) 65.9,30.77 65.9,31.64 63.5,34.04 54.36,34.04 51.53,31.21 50.92,31.21 v1(50.52,30.81)
DDR_D15: length 20.1
  TOP w0.121: U5.M1 53.34,31.21 54.86,31.21 54.99,31.08 54.99,30.86 54.86,30.73 54.48,30.73 54.36,30.61 54.36,30.23 54.48,30.1 55.5,30.1 55.63,30.23 55.63,30.48 55.75,30.61 59.31,30.61 59.44,30.73 59.44,30.99 59.31,31.11 58.04,31.11 57.91,31.24 57.91,31.5 58.04,31.62 59.31,31.62 59.44,31.75 59.44,32 59.31,32.13 58.04,32.13 57.91,32.26 57.91,32.51 58.04,32.64 60.03,32.64 U12.A3
DDR_DQM0: length 23.3
  TOP w0.121: v1(56.13,31.17) 55.7,31.17 55.26,31.61 52.12,31.61 U5.M2 ; v1(65.5,27.97) U12.E7
  BOTTOM w0.121: v1(65.5,27.97) 65.15,27.97 65.02,27.84 65.02,27.3 64.9,27.18 62.87,27.18 62.74,27.3 62.74,28.19 61.98,28.96 61.98,30.48 60.71,31.75 56.77,31.75 56.64,31.62 56.64,29.59 56.52,29.46 55.75,29.46 55.63,29.59 55.63,31.04 55.75,31.17 v1(56.13,31.17)
DDR_DQM1: length 20.2
  TOP w0.121: U5.J2 52.12,29.21 56.52,29.21 56.64,29.34 56.64,30.1 56.77,30.23 59.31,30.23 59.44,30.1 59.44,29.84 59.31,29.72 57.78,29.72 57.66,29.59 57.66,29.34 57.78,29.21 59.31,29.21 59.44,29.08 59.44,28.83 59.31,28.7 57.78,28.7 57.66,28.57 57.66,28.32 57.78,28.19 59.44,28.19 60.01,28.76 61.5,28.76 U12.D3
DDR_DQS0: length 23.3
  TOP w0.095: U5.P1 52.62,32.91 53.76,32.91 54.62,33.78 62.99,33.78 63.12,33.66 63.12,33.43 62.99,33.31 62.01,33.31 61.69,32.99 61.69,32.28 63.22,30.75 63.22,26.53 62.93,26.24 62.75,26.24 62.67,26.32 62.67,26.73 62.6,26.8 62.37,26.8 62.29,26.73 62.29,26.44 62.22,26.37 61.62,26.37 61.54,26.44 61.54,26.69 61.62,26.77 U12.F3
DDR_DQS1: length 20.3
  TOP w0.095: v1(53.85,30.81) 53.45,30.41 U5.L1
  TOP w0.121: v1(65.5,29.57) U12.C7
  BOTTOM w0.095: v1(53.85,30.81) 53.62,31.04 53.62,31.24 53.75,31.37 54.47,31.37 54.76,31.66 54.76,32.04 54.38,32.42 54.38,32.65 54.76,33.03 62.86,33.03 64.14,31.75 64.14,31.37 63.91,31.14 63.64,31.14 63.35,30.85 63.35,30.26 63.64,29.97 65.54,29.97 65.61,29.9 65.61,29.64 65.54,29.57 v1(65.5,29.57)
DDR_DQSN0: length 23.3
  TOP w0.095: U12.G3 63.05,25.97 63.5,26.42 63.5,30.86 61.97,32.39 61.97,32.87 62.12,33.03 63.11,33.03 63.4,33.32 63.4,33.77 63.11,34.06 54.51,34.06 53.64,33.19 52.1,33.19 U5.P2
DDR_DQSN1: length 20.3
  TOP w0.095: U5.L2 52.12,30.81 v1(53.09,30.81)
  TOP w0.121: v1(65.5,30.37) U12.B7
  BOTTOM w0.095: v1(53.09,30.81) 53.34,31.06 53.34,31.36 53.63,31.65 54.36,31.65 54.48,31.78 54.48,31.93 54.1,32.31 54.1,32.77 54.64,33.31 62.97,33.31 64.41,31.87 64.41,31.25 64.02,30.86 63.75,30.86 63.63,30.73 63.63,30.38 63.75,30.25 65.39,30.25 v1(65.5,30.37)
DDR_ODT: length 24.1
  TOP w0.121: U5.G1 53.68,27.21 54.32,27.21 55.12,26.42 55.12,25.53 55.5,25.15 56.13,25.15 56.39,24.89 56.39,21.7 56.49,21.59 56.64,21.59 56.75,21.7 56.75,24.26 56.86,24.37 57.3,24.37 57.4,24.26 57.4,23.62 57.55,23.48 57.55,22.1 57.68,21.97 57.91,21.97 58.04,22.1 58.04,23.75 v1(57.91,23.88) ; v1(59.9,23.16) U12.K1
  LYR3 w0.133: v1(57.91,23.88) 57.91,24.38 57.66,24.64 57.66,25.02 57.78,25.15 58.17,25.15 58.42,24.89 58.42,23.5 58.29,23.37 58.04,23.37 57.91,23.24 57.91,22.99 58.04,22.86 58.93,22.86 59.23,23.16 v1(59.9,23.16)
DDR_RASN: length 24
  TOP w0.121: U5.G4 v1(50.52,26.81) ; v1(61.5,23.96) U12.J3
  LYR3 w0.121: 51.33,24.77 51.17,24.77 50.92,25.02 50.92,25.41 50.72,25.61 50.34,25.61 50.12,25.83 50.12,26.41 v1(50.52,26.81)
  LYR3 w0.133: v1(61.5,23.96) 62.12,23.96 62.51,23.58 62.69,23.58 62.84,23.72 62.84,23.9 62.1,24.64 61.59,24.64 61.35,24.4 59.42,24.4 57.77,26.05 56.5,26.05 54.99,27.56 53.47,27.56 53.34,27.43 53.34,26.53 53.47,26.4 54.24,26.4 54.74,25.91 54.74,25.27 54.23,24.77 51.33,24.77
DDR_RESETN: length 20.7
  TOP w0.121: U5.G2 52.12,27.61 54.43,27.61 55.5,26.54 55.5,25.78 55.75,25.53 56.39,25.53 56.75,25.16 57.89,25.16 58.42,24.64 58.42,21.97 58.67,21.72 58.67,18.03 58.8,17.91 60.24,17.91 v1(60.7,18.36) U12.T2
  BOTTOM w0.121: v1(60.7,18.36) U12.T2 61.96,18.76 62.36,19.16 R97.2
DDR_VREF: length 27.1
  TOP w0.305: v1(59.9,25.57) U12.H1 ; v1(66.3,21.56) U12.M8 ; v1(50.52,28.41) U5.J4
  BOTTOM w0.381: v1(50.52,28.41) 51.07,28.96 54.48,28.96 55.03,28.41 C28.1 55.37,27.43 56.31,26.49 59.36,26.49 59.47,26.6 60.33,26.6 60.34,26.59 62.51,26.59 62.99,26.11 R98.2 ; v1(66.3,21.56) 65.17,21.56 64.77,21.96 C124.1 R100.1 64.01,23.38 63.63,23.76 63.46,23.76 63.45,23.77 63.23,23.77 62.99,24 C123.1 R98.2 ; R98.2 62.4,25.57 61.82,24.99 60.47,24.99 v1(59.9,25.57)
DDR_VTP: length 6.7
  TOP w0.305: v1(51.32,28.41) U5.J3
  BOTTOM w0.381: R22.2 54.86,26.16 54.86,27.69 54.14,28.41 v1(51.32,28.41)
DDR_WEN: length 23.9
  TOP w0.121: U5.B2 51.72,22.97 52.12,22.57 52.12,20.95 52.24,20.83 52.96,20.83 53.47,20.32 53.47,19.58 55.37,17.68 v1(55.37,17.53) ; v1(61.5,22.36) U12.L3
  LYR3 w0.133: v1(55.37,17.53) 55.38,17.52 55.63,17.52 56.77,16.38 62.23,16.38 63.12,17.27 63.12,20.57 63.5,20.95 63.5,21.72 62.48,22.73 61.87,22.73 v1(61.5,22.36)
EHRPWM1A: length 42.2
  TOP w0.121: v1(40.34,38.35) 40.97,38.99 41.63,38.99 42.52,38.1 42.52,35.61 U5.U14
  LYR4 w0.133: P9.14 34.9,4.47 34.9,9.12 35.56,9.78 35.56,18.92 35.43,19.06 35.43,23.11 35.56,23.24 35.56,25.78 36.06,26.29 36.06,27.07 37.24,28.24 37.24,33.55 40.34,36.65 v1(40.34,38.35)
EHRPWM1B: length 36.3
  TOP w0.121: v1(41.72,34.81) U5.T14
  LYR4 w0.133: v1(41.72,34.81) 41.72,35.36 41.09,35.99 40.64,35.99 37.97,33.32 37.97,27.18 36.3,25.5 36.3,22.89 36.49,22.7 36.49,19.39 36.96,18.92 36.96,4.95 P9.16
EHRPWM2A: length 17.2
  TOP w0.121: U5.U10 45.72,35.61 45.72,36.17 45.42,36.48 45.42,37.95 45.99,38.53 45.99,39.2 43.81,41.39 43.81,44.6 44.2,44.98 44.2,48.51 P8.19
